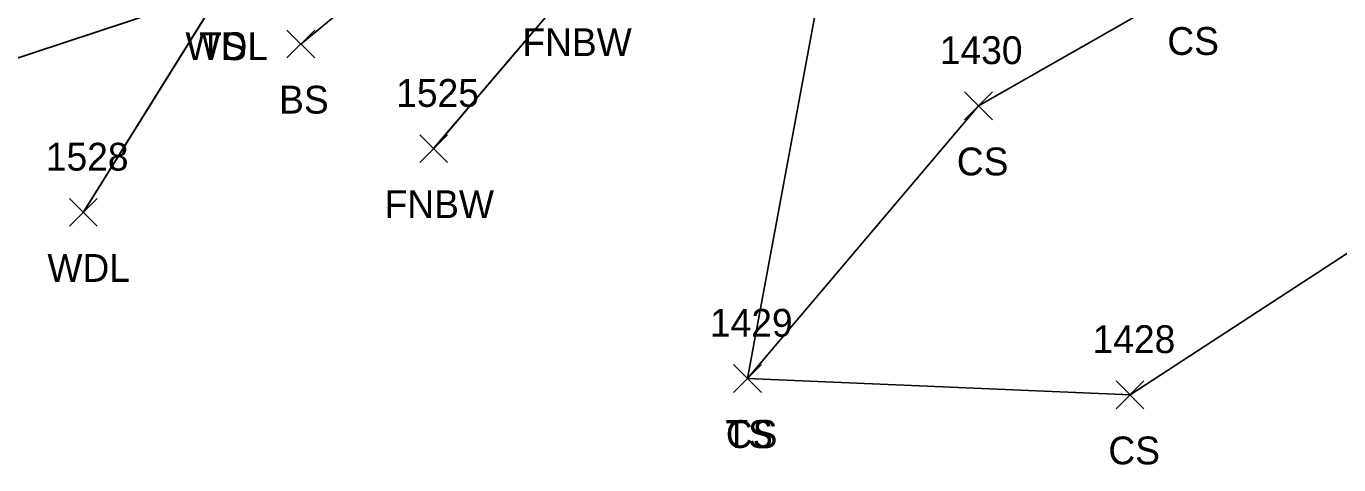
# Model space of a CAD drawing. Extents: x 1415642 to 1422021, y 544543 to 547232.
# Drawn here: x 1416043.1 to 1416137.5, y 546686.8 to 546718.3 of the extents above; entities that cross this region are included whole.
import ezdxf

# ---------------------------------------------------------------- set-up
doc = ezdxf.new("R2010")
doc.units = 0
for name, color, linetype in [('L_A', 7, 'Continuous'), ('L_I', 7, 'Continuous'), ('L_TIC', 7, 'Continuous'), ('LAWA', 7, 'Continuous'), ('LELB', 7, 'Continuous'), ('LFNC', 7, 'Continuous')]:
    doc.layers.add(name, color=color, linetype=linetype)

msp = doc.modelspace()

# ---------------------------------------------------------------- linework, layer by layer
at = {"layer": 'L_TIC'}
for points in [[(1416061.826, 546716.027), (1416063.826, 546718.027)], [(1416063.826, 546716.027), (1416061.826, 546718.027)], [(1416110.597, 546711.582), (1416112.597, 546713.582)], [(1416112.597, 546711.582), (1416110.597, 546713.582)], [(1416071.387, 546708.508), (1416073.387, 546710.508)], [(1416073.387, 546708.508), (1416071.387, 546710.508)], [(1416046.173, 546703.924), (1416048.173, 546705.924)], [(1416048.173, 546703.924), (1416046.173, 546705.924)], [(1416093.974, 546691.98), (1416095.974, 546693.98)], [(1416095.974, 546691.98), (1416093.974, 546693.98)], [(1416093.974, 546691.98), (1416095.974, 546693.98)], [(1416095.974, 546691.98), (1416093.974, 546693.98)], [(1416121.505, 546690.802), (1416123.505, 546692.802)], [(1416123.505, 546690.802), (1416121.505, 546692.802)]]:
    msp.add_lwpolyline(points, dxfattribs=at)
at = {"layer": 'LAWA'}
for points in [[(1416189.468, 546748.093), (1416170.483, 546756.813), (1416159.398, 546761.07), (1416158.818, 546764.495), (1416158.5, 546767.312), (1416157.339, 546771.4), (1416149.111, 546783.522), (1416143.568, 546776.625), (1416135.571, 546781.553), (1416136.009, 546776.955), (1416135.395, 546775.051), (1416133.212, 546773.698), (1416124.824, 546771.254), (1416110.474, 546763.899), (1416099.189, 546751.925), (1416087.771, 546744.353), (1416077.131, 546736.348), (1416057.108, 546720.869), (1416047.173, 546704.924)], [(1416189.464, 546748.092), (1416170.487, 546756.813), (1416159.394, 546761.071), (1416158.815, 546764.495), (1416158.505, 546767.312), (1416157.342, 546771.4), (1416149.113, 546783.521), (1416143.565, 546776.626), (1416135.574, 546781.553), (1416136.011, 546776.955), (1416135.402, 546775.05), (1416133.216, 546773.698), (1416124.826, 546771.255), (1416110.476, 546763.9), (1416099.195, 546751.924), (1416087.779, 546744.35), (1416077.137, 546736.347), (1416057.114, 546720.867), (1416047.178, 546704.926)]]:
    msp.add_lwpolyline(points, dxfattribs=at)
at = {"layer": 'LELB'}
for points in [[(1416094.974, 546692.98), (1416100.915, 546725.021), (1416119.322, 546735.048), (1416143.84, 546740.317), (1416158.08, 546750.444), (1416159.398, 546761.07), (1416139.079, 546763.942), (1416114.009, 546753.752)], [(1416094.979, 546692.982), (1416100.917, 546725.022), (1416119.325, 546735.049), (1416143.845, 546740.318), (1416158.084, 546750.445), (1416159.394, 546761.071), (1416139.085, 546763.941), (1416114.011, 546753.753)], [(1416175.936, 546741.204), (1416165.363, 546727), (1416147.251, 546707.905), (1416122.505, 546691.802), (1416094.974, 546692.98), (1416111.597, 546712.582), (1416126.749, 546721.244), (1416149.596, 546729.765), (1416158.08, 546750.444)], [(1416175.932, 546741.204), (1416165.361, 546727), (1416147.255, 546707.906), (1416122.504, 546691.802), (1416094.979, 546692.982), (1416111.6, 546712.583), (1416126.753, 546721.246), (1416149.597, 546729.766), (1416158.084, 546750.445)], [(1416087.771, 546744.353), (1416076.983, 546728.719), (1416062.826, 546717.027)], [(1416087.779, 546744.35), (1416076.99, 546728.717), (1416062.833, 546717.023)], [(1416057.108, 546720.869), (1416039.042, 546714.911)], [(1416057.114, 546720.867), (1416039.048, 546714.91)]]:
    msp.add_lwpolyline(points, dxfattribs=at)
at = {"layer": 'LFNC'}
for points in [[(1416124.612, 546767.204), (1416114.009, 546753.752), (1416105.919, 546744.351), (1416094.093, 546733.599), (1416082.302, 546721.158), (1416072.387, 546709.508)], [(1416124.618, 546767.203), (1416114.011, 546753.753), (1416105.922, 546744.352), (1416094.099, 546733.598), (1416082.31, 546721.154), (1416072.394, 546709.506)]]:
    msp.add_lwpolyline(points, dxfattribs=at)

# ---------------------------------------------------------------- texts
at = {"layer": 'L_A'}
for s, p in [('WDL', (1416054.526, 546715.869)), ('TS', (1416055.518, 546715.869)), ('FNBW', (1416078.774, 546716.158)), ('CS', (1416125.19, 546716.244)), ('BS', (1416061.267, 546712.027)), ('CS', (1416110.038, 546707.582)), ('FNBW', (1416068.86, 546704.508)), ('WDL', (1416044.59, 546699.924)), ('TS', (1416093.384, 546687.98)), ('CS', (1416093.415, 546687.98)), ('CS', (1416120.946, 546686.802))]:
    msp.add_text(s, height=2, dxfattribs=at).set_placement(p)
at = {"layer": 'L_I'}
for s, p in [('1430', (1416108.818, 546715.582)), ('1525', (1416069.695, 546712.508)), ('1528', (1416044.48, 546707.924)), ('1429', (1416092.273, 546695.98)), ('1429', (1416092.273, 546695.98)), ('1428', (1416119.812, 546694.802))]:
    msp.add_text(s, height=2, dxfattribs=at).set_placement(p)

doc.saveas('drawing.dxf')
